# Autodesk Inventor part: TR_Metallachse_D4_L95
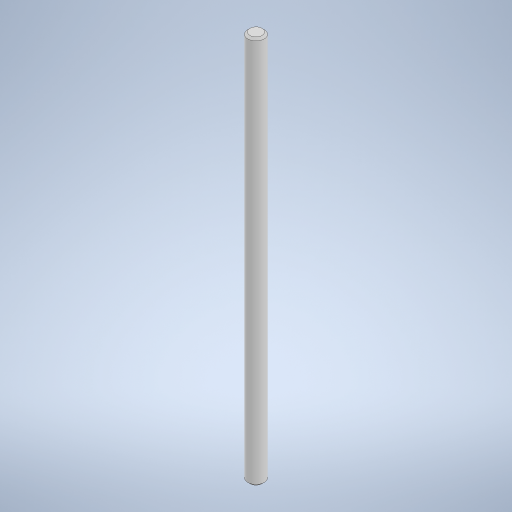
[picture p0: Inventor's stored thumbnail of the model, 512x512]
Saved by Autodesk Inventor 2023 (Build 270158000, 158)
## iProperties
Created: 2023-11
Part Number: TR_Metallachse_D4_L95
Material: Generisch
Document SubType Name: Modeling
Designer: Greiner
Density: 1 g/cm^3
Appearance: Vorgabe
Author: Greiner
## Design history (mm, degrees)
sketch "Skizze1"
  geometry: C1 r 2 at (0, 0); 1 further point
  constraints: 1 centre point, 1 coincident
  dimensions: "d0" = 4 diameter of C1 (= AchsDurchmesser)
extrude "Extrusion1" new body sketch "Skizze1" distance "d1" = 95; taper "d2" = 0 deg
chamfer "Fase1" distance "d3" = 0.5 (= AchsFase); stored, may be unused: second distance "d4" = 2, angle "d5" = 45 deg
node "Volumenkörper1"
other parameters: "Radius" = 2.075 [user parameter], "Fasen" = 0.5 [user parameter], "Dicke" = 0.8 [user parameter], "Breitloch" = 2 [user parameter], "Langloch" = 32 [user parameter], "AchteckUmkreis" = 6 [user parameter], "DAchsAufnahme" = 4.1 [user parameter], "AchsDurchmesser" = 4 [user parameter; used in 1 equation term], "AchsFase" = 0.5 [user parameter; used in 1 equation term]
